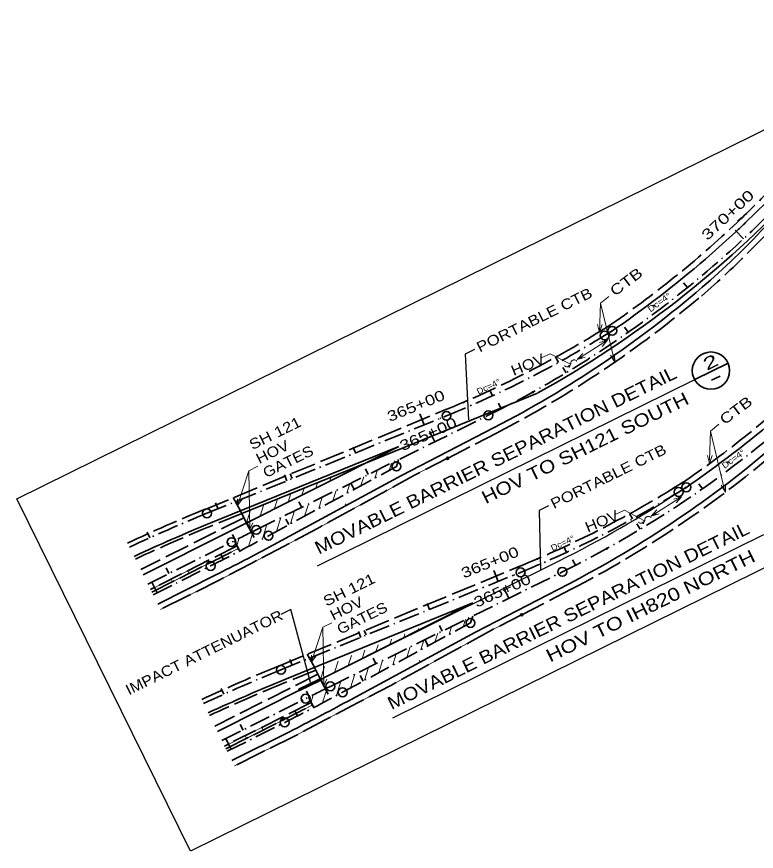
# Model space of a CAD drawing. Extents: x 2356431 to 2371438, y 6972864 to 6982525.
# Drawn here: x 2361285 to 2362282, y 6978847 to 6979972 of the extents above; entities that cross this region are included whole.
import ezdxf
from ezdxf.enums import TextEntityAlignment as Align

# ---------------------------------------------------------------- set-up
doc = ezdxf.new("R2010")
doc.units = 0
doc.header["$LTSCALE"] = 5.6
doc.header["$PDMODE"] = 32
doc.header["$PDSIZE"] = 2.8
doc.linetypes.add('DOT_DASHED', pattern=[7.7, 5, -1.2, 0.3, -1.2])
doc.linetypes.add('LONG_DASHED', pattern=[7.5, 6, -1.5])
for name, color, linetype, lineweight in [('13', 7, 'Continuous', 13), ('14', 7, 'Continuous', 13), ('17', 7, 'Continuous', 35), ('2', 7, 'Continuous', 35), ('21', 7, 'Continuous', 13), ('24', 7, 'Continuous', 13), ('27', 7, 'Continuous', 13), ('28', 7, 'Continuous', 35), ('44', 7, 'Continuous', 13), ('5', 7, 'Continuous', 13), ('6', 7, 'DOT_DASHED', 35)]:
    doc.layers.add(name, color=color, linetype=linetype, lineweight=lineweight)

msp = doc.modelspace()

# ---------------------------------------------------------------- linework, layer by layer
at = {"layer": '13'}
for p, q in [((2362072.027, 6979585.264), (2362083.351, 6979594.356)), ((2362072.027, 6979585.264), (2362070.8, 6979546.142)), ((2362072.027, 6979585.264), (2362091.222, 6979505.864)), ((2362070.8, 6979546.142), (2362068.247, 6979556.924)), ((2362070.8, 6979546.142), (2362074.309, 6979556.653)), ((2362091.221, 6979505.865), (2362085.376, 6979515.278)), ((2362091.222, 6979505.865), (2362091.21, 6979516.946)), ((2362220.275, 6979413.1), (2362231.599, 6979422.192)), ((2362220.275, 6979413.1), (2362219.048, 6979373.978)), ((2362220.275, 6979413.1), (2362239.47, 6979333.7)), ((2362219.026, 6979369.461), (2362216.473, 6979380.243)), ((2362219.026, 6979369.461), (2362222.535, 6979379.972)), ((2361598.016, 6979359.734), (2361582.677, 6979312.967)), ((2361598.016, 6979359.734), (2361610.233, 6979365.704)), ((2361598.016, 6979359.734), (2361599.328, 6979280.714)), ((2362240.538, 6979330.623), (2362234.693, 6979340.036)), ((2362240.539, 6979330.623), (2362240.527, 6979341.704)), ((2361582.677, 6979312.967), (2361582.62, 6979321.963)), ((2361582.677, 6979312.967), (2361589.199, 6979321.284)), ((2361599.328, 6979280.714), (2361595.755, 6979291.209)), ((2361599.328, 6979280.714), (2361603.257, 6979289.599)), ((2361697.852, 6979148.808), (2361710.069, 6979154.778)), ((2361697.852, 6979148.808), (2361682.513, 6979102.041)), ((2361697.852, 6979148.808), (2361699.164, 6979069.788)), ((2361682.513, 6979102.041), (2361682.456, 6979111.037)), ((2361682.513, 6979102.041), (2361689.035, 6979110.358)), ((2361699.164, 6979069.788), (2361695.591, 6979080.283)), ((2361699.164, 6979069.788), (2361703.093, 6979078.673))]:
    msp.add_line(p, q, dxfattribs=at)
for points in [[(2361991.233, 6979511.237), (2362004.466, 6979517.219), (2362031.739, 6979503.26)], [(2362040.424, 6979507.404), (2362039.301, 6979508.322), (2362038.351, 6979508.756), (2362037.483, 6979508.959), (2362036.671, 6979509.004), (2362035.905, 6979508.921), (2362035.179, 6979508.723), (2362034.491, 6979508.418), (2362033.844, 6979507.998), (2362033.243, 6979507.451), (2362032.697, 6979506.745), (2362032.235, 6979505.808), (2362032.061, 6979505.226), (2362031.945, 6979504.389), (2362031.826, 6979503.55), (2362031.653, 6979502.97), (2362031.521, 6979502.646), (2362031.19, 6979502.032), (2362030.907, 6979501.631), (2362030.645, 6979501.326), (2362030.044, 6979500.78), (2362029.397, 6979500.36), (2362028.71, 6979500.054), (2362027.984, 6979499.858), (2362027.217, 6979499.775), (2362026.406, 6979499.818), (2362025.537, 6979500.022), (2362024.893, 6979500.288), (2362024.586, 6979500.456), (2362024.085, 6979500.797), (2362023.465, 6979501.372)], [(2362091.069, 6979300.311), (2362104.302, 6979306.293), (2362131.575, 6979292.334)], [(2362140.26, 6979296.478), (2362139.137, 6979297.396), (2362138.187, 6979297.83), (2362137.319, 6979298.033), (2362136.507, 6979298.078), (2362135.741, 6979297.995), (2362135.015, 6979297.797), (2362134.327, 6979297.492), (2362133.68, 6979297.072), (2362133.079, 6979296.525), (2362132.533, 6979295.819), (2362132.071, 6979294.882), (2362131.897, 6979294.3), (2362131.781, 6979293.463), (2362131.662, 6979292.624), (2362131.489, 6979292.044), (2362131.357, 6979291.72), (2362131.026, 6979291.106), (2362130.743, 6979290.705), (2362130.481, 6979290.4), (2362129.88, 6979289.854), (2362129.233, 6979289.434), (2362128.546, 6979289.128), (2362127.82, 6979288.932), (2362127.053, 6979288.849), (2362126.242, 6979288.892), (2362125.373, 6979289.096), (2362124.729, 6979289.362), (2362124.422, 6979289.53), (2362123.921, 6979289.871), (2362123.301, 6979290.446)]]:
    msp.add_lwpolyline(points, dxfattribs=at)
at = {"layer": '14'}
for p, q in [((2362081.557, 6979535.511), (2362070.936, 6979532.37)), ((2362081.557, 6979535.511), (2362074.184, 6979527.245)), ((2362040.749, 6979509.477), (2362048.164, 6979517.708)), ((2362181.393, 6979324.585), (2362170.772, 6979321.444)), ((2362181.393, 6979324.585), (2362174.02, 6979316.319)), ((2362140.585, 6979298.551), (2362148, 6979306.782))]:
    msp.add_line(p, q, dxfattribs=at)
at = {"layer": '14', "linetype": 'DOT_DASHED', "lineweight": 35}
for p, q in [((2361624.58, 6979272.063), (2361797.034, 6979365.448)), ((2361469.094, 6979192.431), (2361546.575, 6979231.359)), ((2361724.416, 6979061.137), (2361896.87, 6979154.522)), ((2361568.93, 6978981.505), (2361646.411, 6979020.433))]:
    msp.add_line(p, q, dxfattribs=at)
at = {"layer": '14'}
for points in [[(2362081.557, 6979535.511), (2362040.749, 6979509.477), (2362051.387, 6979512.567)], [(2362181.393, 6979324.585), (2362140.585, 6979298.551), (2362151.223, 6979301.641)]]:
    msp.add_lwpolyline(points, dxfattribs=at)
at = {"layer": '14', "linetype": 'DOT_DASHED', "lineweight": 35}
for centre in [(2360260.439, 6981791.217), (2360360.274, 6981580.291)]:
    msp.add_arc(centre, 2864.789, 296.67607, 298.43586, dxfattribs=at)
at = {"layer": '17', "lineweight": 13}
for centre in [(2362143.726, 6979581.67), (2362078.503, 6979535.37), (2362045.978, 6979512.085), (2362029.712, 6979500.448), (2361980.928, 6979465.519), (2362243.562, 6979370.744), (2362178.339, 6979324.444), (2362145.814, 6979301.159), (2362129.548, 6979289.521), (2362080.763, 6979254.593)]:
    msp.add_circle(centre, 1, dxfattribs=at)
at = {"layer": '2'}
for p, q in [((2362295.276, 6979721.222), (2362267.688, 6979694.092)), ((2362254.513, 6979681.646), (2362213.548, 6979644.898)), ((2362199.174, 6979482.46), (2362244.228, 6979504.555)), ((2362221.796, 6979481.52), (2362233.234, 6979487.166)), ((2361987.29, 6979464.152), (2361588.523, 6979301.965)), ((2361803.7, 6979353.137), (2361928.965, 6979417.887)), ((2361800.361, 6979392.442), (2361455.817, 6979219.333)), ((2361800.361, 6979392.442), (2361546.816, 6979289.32)), ((2361797.034, 6979365.448), (2361799.972, 6979374.703)), ((2361631.246, 6979259.752), (2361803.7, 6979353.137)), ((2361577.051, 6979323.394), (2361586.767, 6979305.754)), ((2361586.748, 6979305.561), (2361594.833, 6979289.178)), ((2361594.833, 6979289.178), (2361605.204, 6979269.676)), ((2361585.789, 6979251.314), (2361578.707, 6979265.409)), ((2361475.29, 6979179.876), (2361552.86, 6979218.849)), ((2361903.536, 6979142.211), (2362028.801, 6979206.961)), ((2361900.197, 6979181.516), (2361555.653, 6979008.407)), ((2361900.197, 6979181.516), (2361646.652, 6979078.394)), ((2361896.87, 6979154.522), (2361899.808, 6979163.777)), ((2361731.082, 6979048.826), (2361903.536, 6979142.211)), ((2361676.887, 6979112.468), (2361686.603, 6979094.828)), ((2361686.584, 6979094.635), (2361694.669, 6979078.252)), ((2361694.669, 6979078.252), (2361705.04, 6979058.75)), ((2361685.625, 6979040.388), (2361678.543, 6979054.483)), ((2361575.126, 6978968.95), (2361652.696, 6979007.923))]:
    msp.add_line(p, q, dxfattribs=at)
at = {"layer": '2', "lineweight": 25}
for p, q in [((2361690.8, 6979231.56), (2362199.174, 6979482.46)), ((2361792.105, 6979026.773), (2362292.462, 6979273.717)), ((2361694.669, 6979078.252), (2362016.447, 6979238.311)), ((2361654.647, 6979172.67), (2361641.192, 6979166.029)), ((2361681.359, 6979074.096), (2361654.647, 6979172.67))]:
    msp.add_line(p, q, dxfattribs=at)
at = {"layer": '2', "linetype": 'LONG_DASHED'}
for p, q in [((2361539.381, 6979307.6), (2361861.499, 6979441.067)), ((2361866.036, 6979376.355), (2361932.637, 6979410.78)), ((2361865.984, 6979376.456), (2361821.488, 6979353.649)), ((2361821.424, 6979353.615), (2361777.599, 6979329.543)), ((2361777.535, 6979329.509), (2361733.71, 6979305.437)), ((2361588.523, 6979301.965), (2361548.323, 6979285.615)), ((2361733.646, 6979305.403), (2361689.821, 6979281.331)), ((2361591.293, 6979296.352), (2361452.276, 6979226.506)), ((2361689.821, 6979281.331), (2361645.552, 6979258.086)), ((2361582.299, 6979258.261), (2361465.553, 6979199.605)), ((2361645.552, 6979258.086), (2361601.283, 6979234.841)), ((2361467.324, 6979196.018), (2361544.779, 6979234.933)), ((2361601.282, 6979234.843), (2361557.013, 6979211.598)), ((2361639.217, 6979096.674), (2361961.335, 6979230.141)), ((2361557.014, 6979211.598), (2361512.236, 6979189.349)), ((2361965.872, 6979165.429), (2362032.473, 6979199.854)), ((2361512.237, 6979189.349), (2361478.811, 6979172.741)), ((2361965.82, 6979165.53), (2361921.324, 6979142.723)), ((2361921.26, 6979142.689), (2361877.435, 6979118.617)), ((2361877.371, 6979118.583), (2361833.546, 6979094.511)), ((2361691.129, 6979085.426), (2361552.112, 6979015.58)), ((2361688.359, 6979091.039), (2361648.159, 6979074.689)), ((2361833.482, 6979094.477), (2361789.657, 6979070.405)), ((2361789.657, 6979070.405), (2361745.388, 6979047.16)), ((2361682.135, 6979047.335), (2361565.389, 6978988.679)), ((2361745.388, 6979047.16), (2361701.119, 6979023.915)), ((2361567.16, 6978985.092), (2361644.615, 6979024.007)), ((2361701.118, 6979023.917), (2361656.849, 6979000.672)), ((2361656.85, 6979000.672), (2361612.072, 6978978.423)), ((2361612.073, 6978978.423), (2361578.647, 6978961.815))]:
    msp.add_line(p, q, dxfattribs=at)
at = {"layer": '2', "lineweight": 13}
for p, q in [((2361865.984, 6979376.456), (2361821.488, 6979353.649)), ((2361821.424, 6979353.615), (2361777.599, 6979329.543)), ((2361777.535, 6979329.509), (2361733.71, 6979305.437)), ((2361733.646, 6979305.403), (2361689.821, 6979281.331)), ((2361689.821, 6979281.331), (2361645.552, 6979258.086)), ((2361645.552, 6979258.086), (2361601.283, 6979234.841)), ((2361601.282, 6979234.843), (2361557.013, 6979211.598)), ((2361515.799, 6979224.692), (2361471.121, 6979202.245)), ((2361517.533, 6979221.241), (2361472.855, 6979198.794)), ((2361517.533, 6979221.241), (2361515.798, 6979224.694)), ((2361495.195, 6979210.016), (2361493.46, 6979213.469)), ((2361557.014, 6979211.598), (2361512.236, 6979189.349)), ((2361471.121, 6979202.245), (2361465.615, 6979199.479)), ((2361472.855, 6979198.794), (2361467.325, 6979196.015)), ((2361472.855, 6979198.794), (2361471.12, 6979202.247)), ((2361512.237, 6979189.349), (2361478.811, 6979172.741)), ((2361965.82, 6979165.53), (2361921.324, 6979142.723)), ((2361921.26, 6979142.689), (2361877.435, 6979118.617)), ((2361877.371, 6979118.583), (2361833.546, 6979094.511)), ((2361833.482, 6979094.477), (2361789.657, 6979070.405)), ((2361789.657, 6979070.405), (2361745.388, 6979047.16)), ((2361745.388, 6979047.16), (2361701.119, 6979023.915)), ((2361701.118, 6979023.917), (2361656.849, 6979000.672)), ((2361615.635, 6979013.766), (2361570.957, 6978991.319)), ((2361617.369, 6979010.315), (2361572.691, 6978987.868)), ((2361617.369, 6979010.315), (2361615.634, 6979013.768)), ((2361595.031, 6978999.09), (2361593.296, 6979002.543)), ((2361656.85, 6979000.672), (2361612.072, 6978978.423)), ((2361570.957, 6978991.319), (2361565.451, 6978988.553)), ((2361572.691, 6978987.868), (2361567.161, 6978985.089)), ((2361572.691, 6978987.868), (2361570.956, 6978991.321)), ((2361612.073, 6978978.423), (2361578.647, 6978961.815))]:
    msp.add_line(p, q, dxfattribs=at)
at = {"layer": '2', "lineweight": 25}
msp.add_lwpolyline([(2361285.115, 6979321.851), (2362601.555, 6979971.558), (2362836.023, 6979496.478), (2361519.583, 6978846.77)], close=True, dxfattribs=at)
for points in [[(2361902.334, 6979523.207), (2361889.67, 6979516.957), (2361893.971, 6979428.467)], [(2362002.17, 6979312.281), (2361989.506, 6979306.031), (2361991.14, 6979226.234)]]:
    msp.add_lwpolyline(points, dxfattribs=at)
at = {"layer": '2'}
msp.add_lwpolyline([(2361694.669, 6979078.252), (2361693.317, 6979076.516), (2361666.318, 6979063.289), (2361665.37, 6979065.163), (2361692.268, 6979078.463)], close=True, dxfattribs=at)
msp.add_circle((2362220.986, 6979494.568), 25.166, dxfattribs=at)
at = {"layer": '2', "linetype": 'LONG_DASHED'}
for centre, radius, start, end in [((2361287.072, 6980718.904), 1410.395, 313.40549, 315.67541), ((2361256.679, 6980676.098), 1440.395, 311.35741, 318.66625), ((2361287.072, 6980718.904), 1410.395, 304.27695, 313.40549), ((2361261.94, 6980709.179), 1461.395, 297.31887, 310.34554), ((2361324.824, 6980760.491), 1424.395, 292.13396, 301.7099), ((2361386.908, 6980507.978), 1410.395, 304.27695, 313.40549), ((2361361.776, 6980498.253), 1461.395, 297.31887, 310.34554), ((2361424.66, 6980549.565), 1424.395, 292.13396, 301.7099), ((2362404.989, 6977179.332), 2297.831, 112.13259, 114.97906), ((2362404.991, 6977179.332), 2273.831, 112.13259, 114.96549), ((2360260.439, 6981791.217), 2860.789, 296.67607, 297.55731), ((2362504.825, 6976968.406), 2297.831, 112.13259, 114.97906), ((2362504.826, 6976968.406), 2273.831, 112.13259, 114.96549), ((2360360.274, 6981580.291), 2860.789, 296.67607, 297.55731)]:
    msp.add_arc(centre, radius, start, end, dxfattribs=at)
at = {"layer": '2'}
for centre, radius, start, end in [((2361287.072, 6980718.904), 1418.395, 313.00532, 313.73747), ((2361540.868, 6980387.624), 1027.726, 310.56789, 317.07313), ((2361287.072, 6980718.904), 1418.395, 304.27695, 310.78219), ((2361261.94, 6980709.179), 1453.395, 297.31887, 310.6767), ((2361386.908, 6980507.978), 1418.395, 304.27695, 310.78219), ((2361361.776, 6980498.253), 1453.395, 297.31887, 310.6767), ((2362404.991, 6977179.332), 2277.831, 112.13259, 114.96778), ((2360260.439, 6981791.217), 2878.789, 296.67607, 298.43586), ((2362504.826, 6976968.406), 2277.831, 112.13259, 114.96778), ((2360360.274, 6981580.291), 2878.789, 296.67607, 298.43586)]:
    msp.add_arc(centre, radius, start, end, dxfattribs=at)
for p in [(2361866.036, 6979376.355), (2361965.872, 6979165.429)]:
    msp.add_point(p, dxfattribs=at)
at = {"layer": '21'}
for centre in [(2361887.508, 6979451.194), (2361889.004, 6979452.398), (2361890.5, 6979453.602), (2361571.345, 6979268.569), (2361990.336, 6979242.676), (2361987.344, 6979240.268), (2361988.84, 6979241.472), (2361671.181, 6979057.643)]:
    msp.add_circle(centre, 0.3, dxfattribs=at)
at = {"layer": '24'}
msp.add_line((2362263.255, 6979701.234), (2362256.74, 6979696.581), dxfattribs=at)
at = {"layer": '27'}
for p, q in [((2361856.875, 6979422.364), (2361855.184, 6979423.438)), ((2361855.839, 6979431.335), (2361856.557, 6979429.472)), ((2361843.705, 6979407.509), (2361842.33, 6979408.965)), ((2361825.729, 6979396.547), (2361824.792, 6979398.308)), ((2361955.675, 6979220.409), (2361956.393, 6979218.546)), ((2361956.711, 6979211.438), (2361955.02, 6979212.512)), ((2361943.541, 6979196.583), (2361942.166, 6979198.039)), ((2361925.565, 6979185.621), (2361924.628, 6979187.382))]:
    msp.add_line(p, q, dxfattribs=at)
at = {"layer": '28'}
for p, q in [((2362264.778, 6979672.076), (2362253.857, 6979683.769)), ((2362189.373, 6979606.425), (2362184.019, 6979613.026)), ((2362109.573, 6979546.193), (2362104.692, 6979553.152)), ((2362015.623, 6979505.679), (2362011.523, 6979513.126)), ((2362025.765, 6979491.676), (2362021.381, 6979498.958)), ((2361926.409, 6979460.548), (2361922.839, 6979468.262)), ((2361938.358, 6979443.137), (2361934.493, 6979450.707)), ((2361834.4, 6979421.408), (2361828.372, 6979436.229)), ((2361848.741, 6979398.768), (2361841.661, 6979413.116)), ((2361741.77, 6979383.731), (2361738.567, 6979391.604)), ((2361656.349, 6979349.316), (2361653.782, 6979355.373)), ((2361759.064, 6979354.518), (2361755.303, 6979362.14)), ((2361649.139, 6979346.054), (2361645.936, 6979353.927)), ((2361740.117, 6979334.627), (2361736.069, 6979342.101)), ((2362209.409, 6979335.267), (2362204.528, 6979342.226)), ((2361556.508, 6979308.376), (2361553.306, 6979316.25)), ((2361669.387, 6979310.268), (2361665.626, 6979317.89)), ((2362115.459, 6979294.753), (2362111.359, 6979302.2)), ((2361652.182, 6979287.009), (2361648.134, 6979294.484)), ((2362125.601, 6979280.75), (2362121.217, 6979288.032)), ((2361464.472, 6979269.287), (2361460.984, 6979277.039)), ((2361579.749, 6979265.939), (2361575.946, 6979273.541)), ((2362026.245, 6979249.622), (2362022.675, 6979257.336)), ((2361563.861, 6979240.118), (2361559.994, 6979247.687)), ((2362038.194, 6979232.211), (2362034.329, 6979239.781)), ((2361490.361, 6979221.11), (2361486.55, 6979228.707)), ((2361934.236, 6979210.482), (2361928.208, 6979225.303)), ((2361474.535, 6979195.164), (2361467.352, 6979209.461)), ((2361948.577, 6979187.842), (2361941.497, 6979202.19)), ((2361841.606, 6979172.805), (2361838.403, 6979180.678)), ((2361748.975, 6979135.128), (2361745.772, 6979143.001)), ((2361756.185, 6979138.39), (2361753.618, 6979144.447)), ((2361858.9, 6979143.592), (2361855.139, 6979151.214)), ((2361839.953, 6979123.701), (2361835.905, 6979131.175)), ((2361656.344, 6979097.45), (2361653.142, 6979105.324)), ((2361769.223, 6979099.342), (2361765.462, 6979106.964)), ((2361752.018, 6979076.083), (2361747.97, 6979083.558)), ((2361564.308, 6979058.361), (2361560.82, 6979066.113)), ((2361679.585, 6979055.013), (2361675.782, 6979062.615)), ((2361663.697, 6979029.192), (2361659.83, 6979036.761)), ((2361590.197, 6979010.184), (2361586.386, 6979017.781)), ((2361574.371, 6978984.238), (2361567.188, 6978998.535))]:
    msp.add_line(p, q, dxfattribs=at)
for centre in [(2362077.717, 6979541.924), (2362087.943, 6979548.242), (2361864.512, 6979433.656), (2361920.908, 6979434.378), (2361797.033, 6979365.448), (2362187.779, 6979337.316), (2362177.553, 6979330.998), (2361541.537, 6979302.288), (2361608.101, 6979280.028), (2361624.579, 6979272.063), (2361574.735, 6979263.428), (2361546.574, 6979231.359), (2361964.348, 6979222.73), (2362020.744, 6979223.452), (2361896.869, 6979154.522), (2361641.373, 6979091.362), (2361707.936, 6979069.101), (2361724.415, 6979061.137), (2361674.571, 6979052.502), (2361646.41, 6979020.433)]:
    msp.add_circle(centre, 6, dxfattribs=at)
at = {"layer": '5'}
for p, q in [((2361790.196, 6979369.879), (2361787.099, 6979360.08)), ((2361726.761, 6979358.19), (2361725.737, 6979354.949)), ((2361744.815, 6979365.532), (2361744.44, 6979364.346)), ((2361771.558, 6979360.683), (2361768.127, 6979349.83)), ((2361690.659, 6979343.506), (2361688.337, 6979336.158)), ((2361708.712, 6979350.848), (2361707.038, 6979345.554)), ((2361752.922, 6979351.487), (2361749.157, 6979339.58)), ((2361672.608, 6979336.164), (2361669.636, 6979326.762)), ((2361715.644, 6979333.092), (2361711.214, 6979319.08)), ((2361734.282, 6979342.29), (2361730.186, 6979329.331)), ((2361636.503, 6979321.48), (2361632.234, 6979307.97)), ((2361654.557, 6979328.822), (2361650.936, 6979317.367)), ((2361697.008, 6979323.897), (2361692.245, 6979308.831)), ((2361618.452, 6979314.138), (2361613.533, 6979298.574)), ((2361678.367, 6979314.699), (2361673.274, 6979298.581)), ((2361727.827, 6979315.035), (2361729.099, 6979313.492)), ((2361600.401, 6979306.796), (2361594.833, 6979289.178)), ((2361659.731, 6979305.503), (2361654.303, 6979288.332)), ((2361622.453, 6979287.108), (2361616.361, 6979267.832)), ((2361641.094, 6979296.306), (2361635.333, 6979278.082)), ((2361603.816, 6979277.912), (2361597.391, 6979257.582)), ((2361585.158, 6979268.65), (2361582.038, 6979258.779)), ((2361467.324, 6979196.018), (2361544.779, 6979234.933)), ((2361844.651, 6979154.606), (2361844.276, 6979153.42)), ((2361890.032, 6979158.953), (2361886.935, 6979149.154)), ((2361826.597, 6979147.264), (2361825.573, 6979144.023)), ((2361871.394, 6979149.757), (2361867.963, 6979138.904)), ((2361790.495, 6979132.58), (2361788.173, 6979125.232)), ((2361808.548, 6979139.922), (2361806.874, 6979134.628)), ((2361834.118, 6979131.364), (2361830.022, 6979118.405)), ((2361852.758, 6979140.561), (2361848.993, 6979128.654)), ((2361772.444, 6979125.238), (2361769.472, 6979115.836)), ((2361815.48, 6979122.166), (2361811.05, 6979108.154)), ((2361736.339, 6979110.554), (2361732.07, 6979097.044)), ((2361754.393, 6979117.896), (2361750.772, 6979106.441)), ((2361796.844, 6979112.971), (2361792.081, 6979097.905)), ((2361700.237, 6979095.87), (2361694.669, 6979078.252)), ((2361718.288, 6979103.212), (2361713.369, 6979087.648)), ((2361778.203, 6979103.773), (2361773.11, 6979087.655)), ((2361827.663, 6979104.109), (2361828.935, 6979102.566)), ((2361740.93, 6979085.38), (2361735.169, 6979067.156)), ((2361759.567, 6979094.577), (2361754.139, 6979077.406)), ((2361722.289, 6979076.182), (2361716.197, 6979056.906)), ((2361703.652, 6979066.986), (2361697.227, 6979046.656)), ((2361684.994, 6979057.724), (2361681.874, 6979047.853)), ((2361567.16, 6978985.092), (2361644.615, 6979024.007))]:
    msp.add_line(p, q, dxfattribs=at)
for centre in [(2360260.439, 6981791.217), (2360360.274, 6981580.291)]:
    msp.add_arc(centre, 2860.789, 296.67607, 297.55731, dxfattribs=at)
at = {"layer": '6'}
for p, q in [((2362073.513, 6979548.73), (2362083.739, 6979555.048)), ((2362077.718, 6979541.924), (2362087.944, 6979548.242)), ((2361541.539, 6979302.287), (2361864.513, 6979433.656)), ((2361608.102, 6979280.027), (2361920.909, 6979434.378)), ((2362173.349, 6979337.804), (2362183.575, 6979344.122)), ((2362177.554, 6979330.998), (2362187.78, 6979337.316)), ((2361461.968, 6979206.869), (2361574.736, 6979263.428)), ((2361641.375, 6979091.361), (2361964.349, 6979222.73)), ((2361707.938, 6979069.101), (2362020.745, 6979223.452)), ((2361561.804, 6978995.943), (2361674.572, 6979052.502))]:
    msp.add_line(p, q, dxfattribs=at)
for centre, radius, start, end in [((2361287.074, 6980718.905), 1432.395, 296.26348, 322.17641), ((2361386.91, 6980507.979), 1432.395, 296.26348, 322.17641), ((2361324.824, 6980760.491), 1432.395, 292.13396, 301.7099), ((2361424.66, 6980549.565), 1432.395, 292.13396, 301.7099), ((2362404.992, 6977179.333), 2291.831, 112.1327, 114.97575), ((2364143.437, 6974141.921), 5729.578, 116.26348, 116.63614), ((2362504.827, 6976968.407), 2291.831, 112.1327, 114.97575), ((2364243.273, 6973930.995), 5729.578, 116.26348, 116.63614)]:
    msp.add_arc(centre, radius, start, end, dxfattribs=at)
at = {"layer": '6', "linetype": 'Continuous'}
msp.add_arc((2361291.383, 6980720.837), 1436.395, 298.99553, 316.8666, dxfattribs=at)
at = {"layer": '6', "linetype": 'Continuous', "lineweight": 25}
msp.add_arc((2361382.613, 6980522.838), 1432.395, 296.26348, 303.7165, dxfattribs=at)

# ---------------------------------------------------------------- texts
at = {"layer": '13'}
for s, rotation, width, p in [('CTB', 36.829, 1.3, (2362091.518, 6979594.14)), ('HOV', 22.393, 1.15, (2361955.125, 6979487.284)), ('CTB', 36.829, 1.3, (2362239.4, 6979420.894)), ('SH 121', 26.139, 1.2, (2361602.819, 6979387.356)), ('HOV', 26.139, 1.15, (2361612.07, 6979368.504)), ('GATES', 26.139, 1.15, (2361621.321, 6979349.653)), ('HOV', 22.393, 1.15, (2362054.961, 6979276.358)), ('SH 121', 26.139, 1.2, (2361702.655, 6979176.43)), ('HOV', 26.139, 1.15, (2361711.906, 6979157.578)), ('GATES', 26.139, 1.15, (2361721.157, 6979138.727))]:
    msp.add_text(s, height=14, rotation=rotation, dxfattribs=dict(at, width=width)).set_placement(p)
at = {"layer": '17'}
for rotation, width, p in [(36.1, 1.2, (2362139.463, 6979572.898)), (25.213, 1.15, (2361907.537, 6979462.247)), (36.1, 1.2, (2362239.299, 6979361.972)), (25.213, 1.15, (2362007.373, 6979251.321))]:
    msp.add_text('Dc=4°', height=8, rotation=rotation, dxfattribs=dict(at, width=width)).set_placement(p)
at = {"layer": '2'}
for s, height, width, p in [('PORTABLE CTB', 14, 1.2, (2361909.353, 6979518.793)), ('2', 16.8, 1.55, (2362215.44, 6979494.158)), ('PORTABLE CTB', 14, 1.2, (2362009.189, 6979307.867)), ('IMPACT ATTENUATOR', 14, 1.15, (2361436.339, 6979056.885))]:
    msp.add_text(s, height=height, rotation=26.268, dxfattribs=dict(at, width=width)).set_placement(p)
at = {"layer": '28'}
for s, rotation, width, p in [('370+00', 43.044, 1.4, (2362248.396, 6979699.194)), ('365+00', 22.134, 1.3, (2361825.912, 6979440.659)), ('365+00', 24.384, 1.3, (2361842.702, 6979402.766)), ('365+00', 22.134, 1.3, (2361925.748, 6979229.733)), ('365+00', 24.384, 1.3, (2361942.538, 6979191.84))]:
    msp.add_text(s, height=14, rotation=rotation, dxfattribs=dict(at, width=width)).set_placement(p, align=Align.CENTER)
at = {"layer": '44'}
for s, width, p in [('MOVABLE BARRIER SEPARATION DETAIL', 1.15, (2361934.505, 6979365.896)), ('HOV TO SH121 SOUTH', 1.2, (2362055.191, 6979382.477)), ('MOVABLE BARRIER SEPARATION DETAIL', 1.15, (2362032.558, 6979156.455)), ('HOV TO IH820 NORTH', 1.25, (2362143.403, 6979169.741))]:
    msp.add_text(s, height=17.5, rotation=26.268, dxfattribs=dict(at, width=width)).set_placement(p, align=Align.CENTER)

doc.saveas('drawing.dxf')
